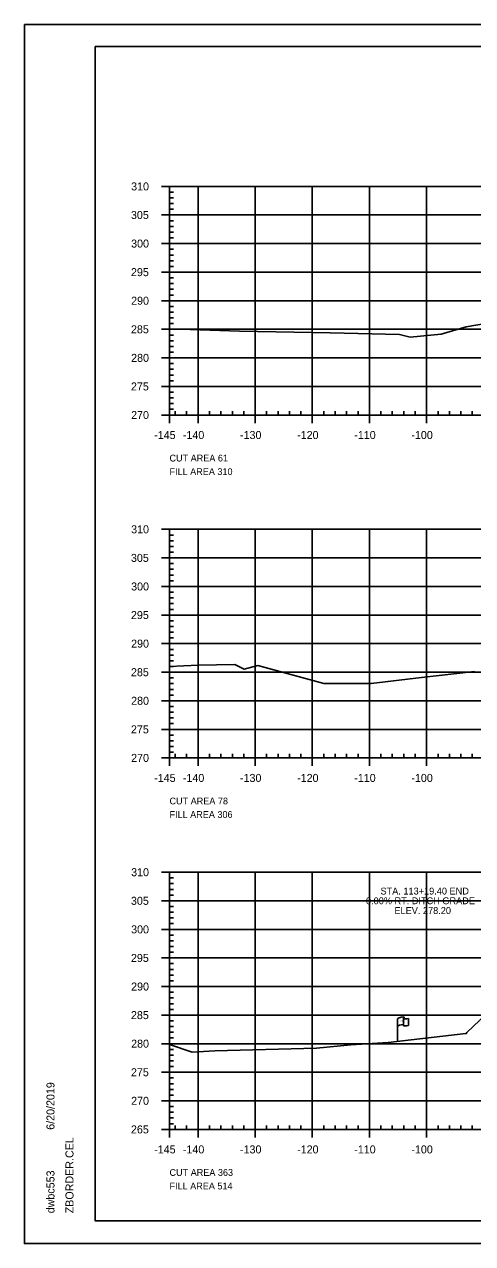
# Model space of a CAD drawing. Extents: x 1370843 to 1371177, y 380307 to 382654.
# Drawn here: x 1370843.3 to 1370921.8, y 381374.2 to 381587.5 of the extents above; entities that cross this region are included whole.
import ezdxf

# ---------------------------------------------------------------- set-up
doc = ezdxf.new("R2010")
doc.units = 0
for name, color, linetype in [('R_Axis', 7, 'Continuous'), ('R_Axis Annot', 7, 'Continuous'), ('R_Border', 7, 'Continuous'), ('R_Border Notes', 7, 'Continuous'), ('R_Exist Surface', 7, 'Continuous'), ('R_Grid', 7, 'Continuous'), ('R_No Plot', 7, 'Continuous'), ('R_ROW', 7, 'Continuous'), ('R_Water Annot', 7, 'Continuous')]:
    doc.layers.add(name, color=color, linetype=linetype)

msp = doc.modelspace()

# ---------------------------------------------------------------- linework, layer by layer
at = {"layer": 'R_Axis'}
for p, q in [((1370867.31, 381559.14), (1370868.71, 381559.14)), ((1370868.71, 381519.14), (1370868.71, 381559.14)), ((1370868.71, 381558.14), (1370869.41, 381558.14)), ((1370868.71, 381557.14), (1370869.41, 381557.14)), ((1370868.71, 381556.14), (1370869.41, 381556.14)), ((1370868.71, 381555.14), (1370869.41, 381555.14)), ((1370867.31, 381554.14), (1370868.71, 381554.14)), ((1370868.71, 381553.14), (1370869.41, 381553.14)), ((1370868.71, 381552.14), (1370869.41, 381552.14)), ((1370868.71, 381551.14), (1370869.41, 381551.14)), ((1370868.71, 381550.14), (1370869.41, 381550.14)), ((1370867.31, 381549.14), (1370868.71, 381549.14)), ((1370868.71, 381548.14), (1370869.41, 381548.14)), ((1370868.71, 381547.14), (1370869.41, 381547.14)), ((1370868.71, 381546.14), (1370869.41, 381546.14)), ((1370867.31, 381544.14), (1370868.71, 381544.14)), ((1370868.71, 381545.14), (1370869.41, 381545.14)), ((1370868.71, 381543.14), (1370869.41, 381543.14)), ((1370868.71, 381542.14), (1370869.41, 381542.14)), ((1370868.71, 381541.14), (1370869.41, 381541.14)), ((1370868.71, 381540.14), (1370869.41, 381540.14)), ((1370867.31, 381539.14), (1370868.71, 381539.14)), ((1370868.71, 381538.14), (1370869.41, 381538.14)), ((1370868.71, 381537.14), (1370869.41, 381537.14)), ((1370868.71, 381536.14), (1370869.41, 381536.14)), ((1370868.71, 381535.14), (1370869.41, 381535.14)), ((1370867.31, 381534.14), (1370868.71, 381534.14)), ((1370868.71, 381533.14), (1370869.41, 381533.14)), ((1370868.71, 381532.14), (1370869.41, 381532.14)), ((1370868.71, 381531.14), (1370869.41, 381531.14)), ((1370867.31, 381529.14), (1370868.71, 381529.14)), ((1370868.71, 381530.14), (1370869.41, 381530.14)), ((1370868.71, 381528.14), (1370869.41, 381528.14)), ((1370868.71, 381527.14), (1370869.41, 381527.14)), ((1370868.71, 381526.14), (1370869.41, 381526.14)), ((1370868.71, 381525.14), (1370869.41, 381525.14)), ((1370867.31, 381524.14), (1370868.71, 381524.14)), ((1370868.71, 381523.14), (1370869.41, 381523.14)), ((1370868.71, 381522.14), (1370869.41, 381522.14)), ((1370868.71, 381521.14), (1370869.41, 381521.14)), ((1370867.31, 381519.14), (1370868.71, 381519.14)), ((1370868.71, 381520.14), (1370869.41, 381520.14)), ((1370868.71, 381519.14), (1370868.71, 381519.84)), ((1370868.71, 381519.14), (1371158.71, 381519.14)), ((1370868.71, 381517.74), (1370868.71, 381519.14)), ((1370869.71, 381519.14), (1370869.71, 381519.84)), ((1370871.71, 381519.14), (1370871.71, 381519.84)), ((1370873.71, 381517.74), (1370873.71, 381519.14)), ((1370875.71, 381519.14), (1370875.71, 381519.84)), ((1370877.71, 381519.14), (1370877.71, 381519.84)), ((1370879.71, 381519.14), (1370879.71, 381519.84)), ((1370881.71, 381519.14), (1370881.71, 381519.84)), ((1370883.71, 381517.74), (1370883.71, 381519.14)), ((1370885.71, 381519.14), (1370885.71, 381519.84)), ((1370887.71, 381519.14), (1370887.71, 381519.84)), ((1370889.71, 381519.14), (1370889.71, 381519.84)), ((1370891.71, 381519.14), (1370891.71, 381519.84)), ((1370893.71, 381517.74), (1370893.71, 381519.14)), ((1370895.71, 381519.14), (1370895.71, 381519.84)), ((1370897.71, 381519.14), (1370897.71, 381519.84)), ((1370899.71, 381519.14), (1370899.71, 381519.84)), ((1370901.71, 381519.14), (1370901.71, 381519.84)), ((1370903.71, 381517.74), (1370903.71, 381519.14)), ((1370905.71, 381519.14), (1370905.71, 381519.84)), ((1370907.71, 381519.14), (1370907.71, 381519.84)), ((1370909.71, 381519.14), (1370909.71, 381519.84)), ((1370911.71, 381519.14), (1370911.71, 381519.84)), ((1370913.71, 381517.74), (1370913.71, 381519.14)), ((1370915.71, 381519.14), (1370915.71, 381519.84)), ((1370917.71, 381519.14), (1370917.71, 381519.84)), ((1370919.71, 381519.14), (1370919.71, 381519.84)), ((1370921.71, 381519.14), (1370921.71, 381519.84)), ((1370867.31, 381499.14), (1370868.71, 381499.14)), ((1370868.71, 381459.14), (1370868.71, 381499.14)), ((1370868.71, 381498.14), (1370869.41, 381498.14)), ((1370868.71, 381497.14), (1370869.41, 381497.14)), ((1370868.71, 381496.14), (1370869.41, 381496.14)), ((1370868.71, 381495.14), (1370869.41, 381495.14)), ((1370867.31, 381494.14), (1370868.71, 381494.14)), ((1370868.71, 381493.14), (1370869.41, 381493.14)), ((1370868.71, 381492.14), (1370869.41, 381492.14)), ((1370868.71, 381491.14), (1370869.41, 381491.14)), ((1370867.31, 381489.14), (1370868.71, 381489.14)), ((1370868.71, 381490.14), (1370869.41, 381490.14)), ((1370868.71, 381488.14), (1370869.41, 381488.14)), ((1370868.71, 381487.14), (1370869.41, 381487.14)), ((1370868.71, 381486.14), (1370869.41, 381486.14)), ((1370867.31, 381484.14), (1370868.71, 381484.14)), ((1370868.71, 381485.14), (1370869.41, 381485.14)), ((1370868.71, 381483.14), (1370869.41, 381483.14)), ((1370868.71, 381482.14), (1370869.41, 381482.14)), ((1370868.71, 381481.14), (1370869.41, 381481.14)), ((1370868.71, 381480.14), (1370869.41, 381480.14)), ((1370867.31, 381479.14), (1370868.71, 381479.14)), ((1370868.71, 381478.14), (1370869.41, 381478.14)), ((1370868.71, 381477.14), (1370869.41, 381477.14)), ((1370868.71, 381476.14), (1370869.41, 381476.14)), ((1370867.31, 381474.14), (1370868.71, 381474.14)), ((1370868.71, 381475.14), (1370869.41, 381475.14)), ((1370868.71, 381473.14), (1370869.41, 381473.14)), ((1370868.71, 381472.14), (1370869.41, 381472.14)), ((1370868.71, 381471.14), (1370869.41, 381471.14)), ((1370867.31, 381469.14), (1370868.71, 381469.14)), ((1370868.71, 381470.14), (1370869.41, 381470.14)), ((1370868.71, 381468.14), (1370869.41, 381468.14)), ((1370868.71, 381467.14), (1370869.41, 381467.14)), ((1370868.71, 381466.14), (1370869.41, 381466.14)), ((1370868.71, 381465.14), (1370869.41, 381465.14)), ((1370867.31, 381464.14), (1370868.71, 381464.14)), ((1370868.71, 381463.14), (1370869.41, 381463.14)), ((1370868.71, 381462.14), (1370869.41, 381462.14)), ((1370868.71, 381461.14), (1370869.41, 381461.14)), ((1370867.31, 381459.14), (1370868.71, 381459.14)), ((1370868.71, 381460.14), (1370869.41, 381460.14)), ((1370868.71, 381459.14), (1370868.71, 381459.84)), ((1370868.71, 381459.14), (1371158.71, 381459.14)), ((1370868.71, 381457.74), (1370868.71, 381459.14)), ((1370869.71, 381459.14), (1370869.71, 381459.84)), ((1370871.71, 381459.14), (1370871.71, 381459.84)), ((1370873.71, 381457.74), (1370873.71, 381459.14)), ((1370875.71, 381459.14), (1370875.71, 381459.84)), ((1370877.71, 381459.14), (1370877.71, 381459.84)), ((1370879.71, 381459.14), (1370879.71, 381459.84)), ((1370881.71, 381459.14), (1370881.71, 381459.84)), ((1370883.71, 381457.74), (1370883.71, 381459.14)), ((1370885.71, 381459.14), (1370885.71, 381459.84)), ((1370887.71, 381459.14), (1370887.71, 381459.84)), ((1370889.71, 381459.14), (1370889.71, 381459.84)), ((1370891.71, 381459.14), (1370891.71, 381459.84)), ((1370893.71, 381457.74), (1370893.71, 381459.14)), ((1370895.71, 381459.14), (1370895.71, 381459.84)), ((1370897.71, 381459.14), (1370897.71, 381459.84)), ((1370899.71, 381459.14), (1370899.71, 381459.84)), ((1370901.71, 381459.14), (1370901.71, 381459.84)), ((1370903.71, 381457.74), (1370903.71, 381459.14)), ((1370905.71, 381459.14), (1370905.71, 381459.84)), ((1370907.71, 381459.14), (1370907.71, 381459.84)), ((1370909.71, 381459.14), (1370909.71, 381459.84)), ((1370911.71, 381459.14), (1370911.71, 381459.84)), ((1370913.71, 381457.74), (1370913.71, 381459.14)), ((1370915.71, 381459.14), (1370915.71, 381459.84)), ((1370917.71, 381459.14), (1370917.71, 381459.84)), ((1370919.71, 381459.14), (1370919.71, 381459.84)), ((1370921.71, 381459.14), (1370921.71, 381459.84)), ((1370867.31, 381439.14), (1370868.71, 381439.14)), ((1370868.71, 381394.14), (1370868.71, 381439.14)), ((1370868.71, 381438.14), (1370869.41, 381438.14)), ((1370868.71, 381437.14), (1370869.41, 381437.14)), ((1370868.71, 381436.14), (1370869.41, 381436.14)), ((1370868.71, 381435.14), (1370869.41, 381435.14)), ((1370867.31, 381434.14), (1370868.71, 381434.14)), ((1370868.71, 381433.14), (1370869.41, 381433.14)), ((1370868.71, 381432.14), (1370869.41, 381432.14)), ((1370868.71, 381431.14), (1370869.41, 381431.14)), ((1370867.31, 381429.14), (1370868.71, 381429.14)), ((1370868.71, 381430.14), (1370869.41, 381430.14)), ((1370868.71, 381428.14), (1370869.41, 381428.14)), ((1370868.71, 381427.14), (1370869.41, 381427.14)), ((1370868.71, 381426.14), (1370869.41, 381426.14)), ((1370868.71, 381425.14), (1370869.41, 381425.14)), ((1370867.31, 381424.14), (1370868.71, 381424.14)), ((1370868.71, 381423.14), (1370869.41, 381423.14)), ((1370868.71, 381422.14), (1370869.41, 381422.14)), ((1370868.71, 381421.14), (1370869.41, 381421.14)), ((1370868.71, 381420.14), (1370869.41, 381420.14)), ((1370867.31, 381419.14), (1370868.71, 381419.14)), ((1370868.71, 381418.14), (1370869.41, 381418.14)), ((1370868.71, 381417.14), (1370869.41, 381417.14)), ((1370868.71, 381416.14), (1370869.41, 381416.14)), ((1370867.31, 381414.14), (1370868.71, 381414.14)), ((1370868.71, 381415.14), (1370869.41, 381415.14)), ((1370868.71, 381413.14), (1370869.41, 381413.14)), ((1370868.71, 381412.14), (1370869.41, 381412.14)), ((1370868.71, 381411.14), (1370869.41, 381411.14)), ((1370868.71, 381410.14), (1370869.41, 381410.14)), ((1370867.31, 381409.14), (1370868.71, 381409.14)), ((1370868.71, 381408.14), (1370869.41, 381408.14)), ((1370868.71, 381407.14), (1370869.41, 381407.14)), ((1370868.71, 381406.14), (1370869.41, 381406.14)), ((1370868.71, 381405.14), (1370869.41, 381405.14)), ((1370867.31, 381404.14), (1370868.71, 381404.14)), ((1370868.71, 381403.14), (1370869.41, 381403.14)), ((1370868.71, 381402.14), (1370869.41, 381402.14)), ((1370868.71, 381401.14), (1370869.41, 381401.14)), ((1370867.31, 381399.14), (1370868.71, 381399.14)), ((1370868.71, 381400.14), (1370869.41, 381400.14)), ((1370868.71, 381398.14), (1370869.41, 381398.14)), ((1370868.71, 381397.14), (1370869.41, 381397.14)), ((1370868.71, 381396.14), (1370869.41, 381396.14)), ((1370868.71, 381395.14), (1370869.41, 381395.14)), ((1370868.71, 381394.14), (1370868.71, 381394.84)), ((1370869.71, 381394.14), (1370869.71, 381394.84)), ((1370871.71, 381394.14), (1370871.71, 381394.84)), ((1370875.71, 381394.14), (1370875.71, 381394.84)), ((1370877.71, 381394.14), (1370877.71, 381394.84)), ((1370879.71, 381394.14), (1370879.71, 381394.84)), ((1370881.71, 381394.14), (1370881.71, 381394.84)), ((1370885.71, 381394.14), (1370885.71, 381394.84)), ((1370887.71, 381394.14), (1370887.71, 381394.84)), ((1370889.71, 381394.14), (1370889.71, 381394.84)), ((1370891.71, 381394.14), (1370891.71, 381394.84)), ((1370895.71, 381394.14), (1370895.71, 381394.84)), ((1370897.71, 381394.14), (1370897.71, 381394.84)), ((1370899.71, 381394.14), (1370899.71, 381394.84)), ((1370901.71, 381394.14), (1370901.71, 381394.84)), ((1370905.71, 381394.14), (1370905.71, 381394.84)), ((1370907.71, 381394.14), (1370907.71, 381394.84)), ((1370909.71, 381394.14), (1370909.71, 381394.84)), ((1370911.71, 381394.14), (1370911.71, 381394.84)), ((1370915.71, 381394.14), (1370915.71, 381394.84)), ((1370917.71, 381394.14), (1370917.71, 381394.84)), ((1370919.71, 381394.14), (1370919.71, 381394.84)), ((1370921.71, 381394.14), (1370921.71, 381394.84)), ((1370867.31, 381394.14), (1370868.71, 381394.14)), ((1370868.71, 381394.14), (1371158.71, 381394.14)), ((1370868.71, 381392.74), (1370868.71, 381394.14)), ((1370873.71, 381392.74), (1370873.71, 381394.14)), ((1370883.71, 381392.74), (1370883.71, 381394.14)), ((1370893.71, 381392.74), (1370893.71, 381394.14)), ((1370903.71, 381392.74), (1370903.71, 381394.14)), ((1370913.71, 381392.74), (1370913.71, 381394.14))]:
    msp.add_line(p, q, dxfattribs=at)
at = {"layer": 'R_Border'}
for p, q in [((1370855.71, 381583.6), (1371171.89, 381583.6)), ((1370855.71, 381378.14), (1370855.71, 381583.6)), ((1370855.71, 381378.14), (1370855.71, 381378.14)), ((1371171.89, 381378.14), (1370855.71, 381378.14))]:
    msp.add_line(p, q, dxfattribs=at)
at = {"layer": 'R_Exist Surface'}
for points in [[(1370868.71, 381534.21), (1370870.58, 381534.14), (1370880.94, 381533.84), (1370896.85, 381533.52), (1370908.94, 381533.23), (1370910.85, 381532.76), (1370916.27, 381533.27), (1370920.65, 381534.56), (1370932.5, 381536.64)], [(1370868.71, 381475.16), (1370873.75, 381475.37), (1370880.15, 381475.5), (1370881.79, 381474.65), (1370884.17, 381475.3), (1370895.72, 381472.15), (1370904.02, 381472.15), (1370912.82, 381473.19), (1370922.1, 381474.29)], [(1370868.71, 381408.99), (1370872.67, 381407.67), (1370876.63, 381407.87), (1370894.42, 381408.35), (1370900.45, 381408.92), (1370906.96, 381409.34), (1370920.58, 381410.93), (1370920.65, 381410.92), (1370920.78, 381411.07), (1370924.13, 381414.31)]]:
    msp.add_lwpolyline(points, dxfattribs=at)
at = {"layer": 'R_Grid'}
for p, q in [((1370868.71, 381559.14), (1371158.71, 381559.14)), ((1370868.71, 381519.14), (1370868.71, 381559.14)), ((1370873.71, 381519.14), (1370873.71, 381559.14)), ((1370883.71, 381519.14), (1370883.71, 381559.14)), ((1370893.71, 381519.14), (1370893.71, 381559.14)), ((1370903.71, 381519.14), (1370903.71, 381559.14)), ((1370913.71, 381519.14), (1370913.71, 381559.14)), ((1370868.71, 381554.14), (1371158.71, 381554.14)), ((1370868.71, 381549.14), (1371158.71, 381549.14)), ((1370868.71, 381544.14), (1371158.71, 381544.14)), ((1370868.71, 381539.14), (1371158.71, 381539.14)), ((1370868.71, 381534.14), (1371158.71, 381534.14)), ((1370868.71, 381529.14), (1371158.71, 381529.14)), ((1370868.71, 381524.14), (1371158.71, 381524.14)), ((1370868.71, 381519.14), (1371158.71, 381519.14)), ((1370868.71, 381499.14), (1371158.71, 381499.14)), ((1370868.71, 381459.14), (1370868.71, 381499.14)), ((1370873.71, 381459.14), (1370873.71, 381499.14)), ((1370883.71, 381459.14), (1370883.71, 381499.14)), ((1370893.71, 381459.14), (1370893.71, 381499.14)), ((1370903.71, 381459.14), (1370903.71, 381499.14)), ((1370913.71, 381459.14), (1370913.71, 381499.14)), ((1370868.71, 381494.14), (1371158.71, 381494.14)), ((1370868.71, 381489.14), (1371158.71, 381489.14)), ((1370868.71, 381484.14), (1371158.71, 381484.14)), ((1370868.71, 381479.14), (1371158.71, 381479.14)), ((1370868.71, 381474.14), (1371158.71, 381474.14)), ((1370868.71, 381469.14), (1371158.71, 381469.14)), ((1370868.71, 381464.14), (1371158.71, 381464.14)), ((1370868.71, 381459.14), (1371158.71, 381459.14)), ((1370868.71, 381439.14), (1371158.71, 381439.14)), ((1370868.71, 381394.14), (1370868.71, 381439.14)), ((1370873.71, 381394.14), (1370873.71, 381439.14)), ((1370883.71, 381394.14), (1370883.71, 381439.14)), ((1370893.71, 381394.14), (1370893.71, 381439.14)), ((1370903.71, 381394.14), (1370903.71, 381439.14)), ((1370913.71, 381394.14), (1370913.71, 381439.14)), ((1370868.71, 381434.14), (1371158.71, 381434.14)), ((1370868.71, 381429.14), (1371158.71, 381429.14)), ((1370868.71, 381424.14), (1371158.71, 381424.14)), ((1370868.71, 381419.14), (1371158.71, 381419.14)), ((1370868.71, 381414.14), (1371158.71, 381414.14)), ((1370868.71, 381409.14), (1371158.71, 381409.14)), ((1370868.71, 381404.14), (1371158.71, 381404.14)), ((1370868.71, 381399.14), (1371158.71, 381399.14)), ((1370868.71, 381394.14), (1371158.71, 381394.14))]:
    msp.add_line(p, q, dxfattribs=at)
at = {"layer": 'R_No Plot'}
for p, q in [((1370843.31, 381587.49), (1371176.64, 381587.49)), ((1370843.31, 381374.16), (1371176.64, 381374.16))]:
    msp.add_line(p, q, dxfattribs=at)
for points in [[(1370843.3, 381587.49), (1371176.64, 381587.49), (1371176.64, 381374.16), (1370843.3, 381374.16)], [(1371089.63, 381583.6), (1371089.63, 381573.72), (1371125.36, 381573.72), (1371125.36, 381570.8), (1371148.56, 381570.8), (1371148.56, 381546.47), (1371171.89, 381546.47), (1371171.89, 381378.14), (1370855.71, 381378.14), (1370855.71, 381583.6)]]:
    msp.add_lwpolyline(points, close=True, dxfattribs=at)
at = {"layer": 'R_ROW'}
for p, q in [((1370909.64, 381413.58), (1370909.64, 381413.56)), ((1370909.64, 381413.56), (1370909.64, 381412.34)), ((1370909.8, 381413.73), (1370909.8, 381413.49)), ((1370910.57, 381413.54), (1370910.57, 381412.3)), ((1370908.64, 381409.53), (1370908.64, 381413.48))]:
    msp.add_line(p, q, dxfattribs=at)
for centre, radius, start, end in [((1370909.72, 381413.58), 0.078, 88.6458, 274.2828), ((1370909.73, 381413.73), 0.0783, 263.0712, 93.9564), ((1370909.72, 381412.34), 0.0783, 180, 273.9564)]:
    msp.add_arc(centre, radius, start, end, dxfattribs=at)
for centre, major_axis, ratio, start_param, end_param in [((1370910.22, 381413.53), (-1.58, -0.04), 0.19887, 5.030368, 6.283185), ((1370910.93, 381413.64), (-1.23, -0.13), 0.052933, 0.159456, 1.268315), ((1370910.22, 381412.21), (-1.58, -0.04), 0.19887, 5.083035, 6.194897), ((1370910.93, 381412.4), (-1.23, -0.13), 0.052933, 0.159456, 1.268315)]:
    msp.add_ellipse(centre, major_axis=major_axis, ratio=ratio, start_param=start_param, end_param=end_param, dxfattribs=at)

# ---------------------------------------------------------------- texts
at = {"layer": 'R_Axis Annot'}
for s, p in [('310', (1370861.99, 381558.44)), ('305', (1370861.96, 381553.44)), ('300', (1370861.99, 381548.44)), ('295', (1370861.96, 381543.44)), ('290', (1370861.99, 381538.44)), ('285', (1370861.96, 381533.44)), ('280', (1370861.99, 381528.44)), ('275', (1370861.96, 381523.44)), ('270', (1370861.99, 381518.44)), ('-145', (1370866.03, 381514.94)), ('-140', (1370871.05, 381514.94)), ('-130', (1370881.05, 381514.94)), ('-120', (1370891.05, 381514.94)), ('-110', (1370901.05, 381514.94)), ('-100', (1370911.05, 381514.94)), ('310', (1370861.99, 381498.44)), ('305', (1370861.96, 381493.44)), ('300', (1370861.99, 381488.44)), ('295', (1370861.96, 381483.44)), ('290', (1370861.99, 381478.44)), ('285', (1370861.96, 381473.44)), ('280', (1370861.99, 381468.44)), ('275', (1370861.96, 381463.44)), ('270', (1370861.99, 381458.44)), ('-145', (1370866.03, 381454.94)), ('-140', (1370871.05, 381454.94)), ('-130', (1370881.05, 381454.94)), ('-120', (1370891.05, 381454.94)), ('-110', (1370901.05, 381454.94)), ('-100', (1370911.05, 381454.94)), ('310', (1370861.99, 381438.44)), ('305', (1370861.96, 381433.44)), ('300', (1370861.99, 381428.44)), ('295', (1370861.96, 381423.44)), ('290', (1370861.99, 381418.44)), ('285', (1370861.96, 381413.44)), ('280', (1370861.99, 381408.44)), ('275', (1370861.96, 381403.44)), ('270', (1370861.99, 381398.44)), ('265', (1370861.96, 381393.44)), ('-145', (1370866.03, 381389.94)), ('-140', (1370871.05, 381389.94)), ('-130', (1370881.05, 381389.94)), ('-120', (1370891.05, 381389.94)), ('-110', (1370901.05, 381389.94)), ('-100', (1370911.05, 381389.94))]:
    msp.add_text(s, height=1.4, dxfattribs=at).set_placement(p)
at = {"layer": 'R_Border'}
for s, p in [('6/20/2019', (1370848.57, 381394.07)), ('ZBORDER.CEL', (1370851.9, 381379.46)), ('dwbc553', (1370848.57, 381379.46))]:
    msp.add_text(s, height=1.4, rotation=90, dxfattribs=at).set_placement(p)
at = {"layer": 'R_Border Notes'}
for s, p in [('CUT AREA 61', (1370868.71, 381511.01)), ('FILL AREA 310', (1370868.71, 381508.64)), ('CUT AREA 78', (1370868.71, 381451.01)), ('FILL AREA 306', (1370868.71, 381448.64)), ('CUT AREA 363', (1370868.71, 381386.01)), ('FILL AREA 514', (1370868.71, 381383.64))]:
    msp.add_text(s, height=1.1875, dxfattribs=at).set_placement(p)
at = {"layer": 'R_ROW'}
for s, height, rotation, p in [('DWB 11-9-07', 0.001, 90, (1370909.8, 381413.49)), ('R ', 0.2, 9.9884, (1370909.16, 381412.99)), (' O', 0.2, 9.9884, (1370909.31, 381413.03)), ('W', 0.2, 351.1788, (1370909.64, 381412.86)), ('DWB 11-9-07', 0.001, 5.0717, (1370910.56, 381412.3)), ('DWB 11-9-07', 0.001, 90, (1370908.64, 381409.53))]:
    msp.add_text(s, height=height, rotation=rotation, dxfattribs=at).set_placement(p)
at = {"layer": 'R_Water Annot'}
for s, p in [('STA. 113+19.40 END', (1370905.64, 381435.24)), ('0.00% RT. DITCH GRADE', (1370903.1, 381433.54)), ('ELEV. 278.20', (1370908.08, 381431.84))]:
    msp.add_text(s, height=1.2, dxfattribs=at).set_placement(p)

doc.saveas('drawing.dxf')
